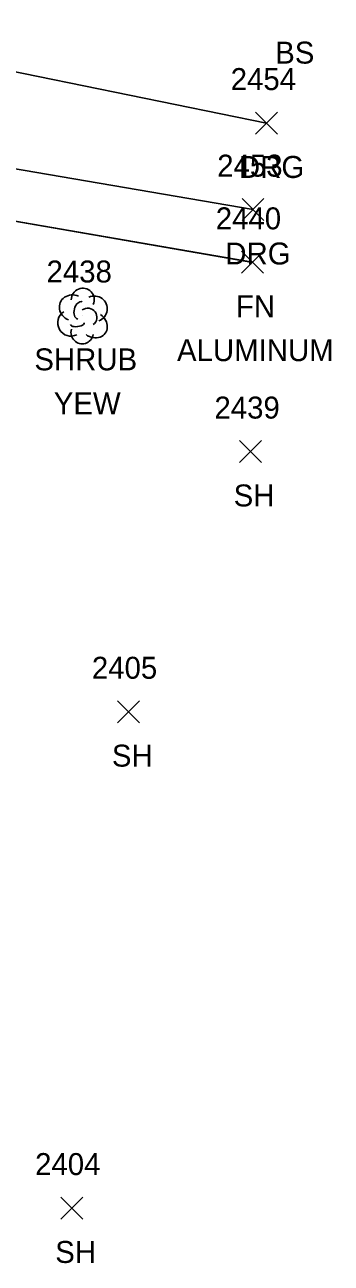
# Model space of a CAD drawing. Extents: x 1554668 to 1563881, y 831386 to 834374.
# Drawn here: x 1562232.7 to 1562260.6, y 832108.4 to 832221.1 of the extents above; entities that cross this region are included whole.
import ezdxf

# ---------------------------------------------------------------- set-up
doc = ezdxf.new("R2010")
doc.units = 0
for name, color, linetype in [('L_A', 7, 'Continuous'), ('L_C', 7, 'Continuous'), ('L_I', 7, 'Continuous'), ('L_TIC', 7, 'Continuous'), ('LFNC', 7, 'Continuous'), ('LSH', 7, 'Continuous'), ('R_A', 7, 'Continuous'), ('R_I', 7, 'Continuous'), ('R_TIC', 7, 'Continuous'), ('RDG', 7, 'Continuous')]:
    doc.layers.add(name, color=color, linetype=linetype)

msp = doc.modelspace()

# ---------------------------------------------------------------- linework, layer by layer
at = {"layer": 'L_TIC'}
for points in [[(1562252.47, 832198.52), (1562254.47, 832200.52)], [(1562254.47, 832198.52), (1562252.47, 832200.52)], [(1562252.27, 832181.29), (1562254.27, 832183.29)], [(1562254.27, 832181.29), (1562252.27, 832183.29)], [(1562241.17, 832157.6), (1562243.17, 832159.6)], [(1562243.17, 832157.6), (1562241.17, 832159.6)], [(1562236.01, 832112.41), (1562238.01, 832114.41)], [(1562238.01, 832112.41), (1562236.01, 832114.41)]]:
    msp.add_lwpolyline(points, dxfattribs=at)
at = {"layer": 'LFNC'}
for points in [[(1562253.47, 832199.52), (1562225.14, 832204.43)], [(1562253.48, 832199.51), (1562225.15, 832204.43)], [(1562253.48, 832199.51), (1562225.15, 832204.43)], [(1562253.48, 832199.51), (1562225.15, 832204.43)]]:
    msp.add_lwpolyline(points, dxfattribs=at)
at = {"layer": 'LSH'}
msp.add_line((1562237.97, 832194.68), (1562237.97, 832194.68), dxfattribs=at)
msp.add_line((1562237.97, 832194.68), (1562237.97, 832194.68), dxfattribs=at)
msp.add_arc((1562238.01, 832196.11), 1.05, 335.5272, 180.9563, dxfattribs=at)
for centre, major_axis, ratio, start_param, end_param in [((1562237.17, 832195.35), (1.21, -0.51), 0.895232, 1.570796, 4.712389), ((1562239.01, 832195.26), (-1.14, -0.48), 0.949671, 1.570796, 4.712389), ((1562236.88, 832193.97), (0.58, -1.04), 0.959034, 3.141593, 6.283185), ((1562237.76, 832195.14), (-0.208, -0.792), 0.645439, 3.141593, 6.283185), ((1562238.47, 832194.51), (-0.5, 0.667), 0.989748, 3.141593, 6.283185), ((1562237.51, 832193.93), (-0.625, -0.083), 0.423636, 0, 3.141593), ((1562238.97, 832193.85), (-1.09, 0.79), 0.841452, 1.570796, 4.712389), ((1562237.97, 832193.18), (0.26, 1.06), 0.942809, 1.570796, 4.712389)]:
    msp.add_ellipse(centre, major_axis=major_axis, ratio=ratio, start_param=start_param, end_param=end_param, dxfattribs=at)
at = {"layer": 'R_TIC'}
for points in [[(1562253.74, 832211.2), (1562255.74, 832213.2)], [(1562255.74, 832211.2), (1562253.74, 832213.2)], [(1562252.51, 832203.32), (1562254.51, 832205.32)], [(1562254.51, 832203.32), (1562252.51, 832205.32)]]:
    msp.add_lwpolyline(points, dxfattribs=at)
at = {"layer": 'RDG'}
for points in [[(1562254.74, 832212.2), (1562221.44, 832218.99), (1562209.11, 832222.87), (1562197.45, 832227.32)], [(1562254.75, 832212.19), (1562221.45, 832218.99), (1562209.11, 832222.87), (1562197.45, 832227.31)], [(1562254.75, 832212.19), (1562221.45, 832218.99), (1562209.11, 832222.87), (1562197.45, 832227.31)], [(1562254.75, 832212.19), (1562221.45, 832218.99), (1562209.11, 832222.87), (1562197.45, 832227.31)], [(1562195.25, 832213.83), (1562204.24, 832212.67), (1562226.7, 832208.9), (1562253.51, 832204.32)], [(1562195.25, 832213.83), (1562204.24, 832212.67), (1562226.7, 832208.9), (1562253.51, 832204.32)], [(1562195.25, 832213.83), (1562204.24, 832212.67), (1562226.7, 832208.9), (1562253.51, 832204.32)], [(1562195.25, 832213.83), (1562204.24, 832212.68), (1562226.7, 832208.9), (1562253.51, 832204.32)]]:
    msp.add_lwpolyline(points, dxfattribs=at)

# ---------------------------------------------------------------- texts
at = {"layer": 'L_A'}
for s, p in [('BS', (1562255.53, 832217.61)), ('FN', (1562251.95, 832194.52)), ('SHRUB', (1562233.6, 832189.68)), ('SH', (1562251.75, 832177.29)), ('SH', (1562240.66, 832153.6)), ('SH', (1562235.5, 832108.41))]:
    msp.add_text(s, height=2, dxfattribs=at).set_placement(p)
at = {"layer": 'L_C'}
for s, p in [('ALUMINUM', (1562246.59, 832190.52)), ('YEW', (1562235.37, 832185.68))]:
    msp.add_text(s, height=2, dxfattribs=at).set_placement(p)
at = {"layer": 'L_I'}
for s, p in [('2440', (1562250.12, 832202.52)), ('2438', (1562234.71, 832197.68)), ('2439', (1562250, 832185.29)), ('2405', (1562238.84, 832161.6)), ('2404', (1562233.67, 832116.41))]:
    msp.add_text(s, height=2, dxfattribs=at).set_placement(p)
at = {"layer": 'R_A'}
for p in [(1562252.23, 832207.2), (1562250.99, 832199.32)]:
    msp.add_text('DRG', height=2, dxfattribs=at).set_placement(p)
at = {"layer": 'R_I'}
for s, p in [('2454', (1562251.48, 832215.2)), ('2453', (1562250.25, 832207.32))]:
    msp.add_text(s, height=2, dxfattribs=at).set_placement(p)

doc.saveas('drawing.dxf')
